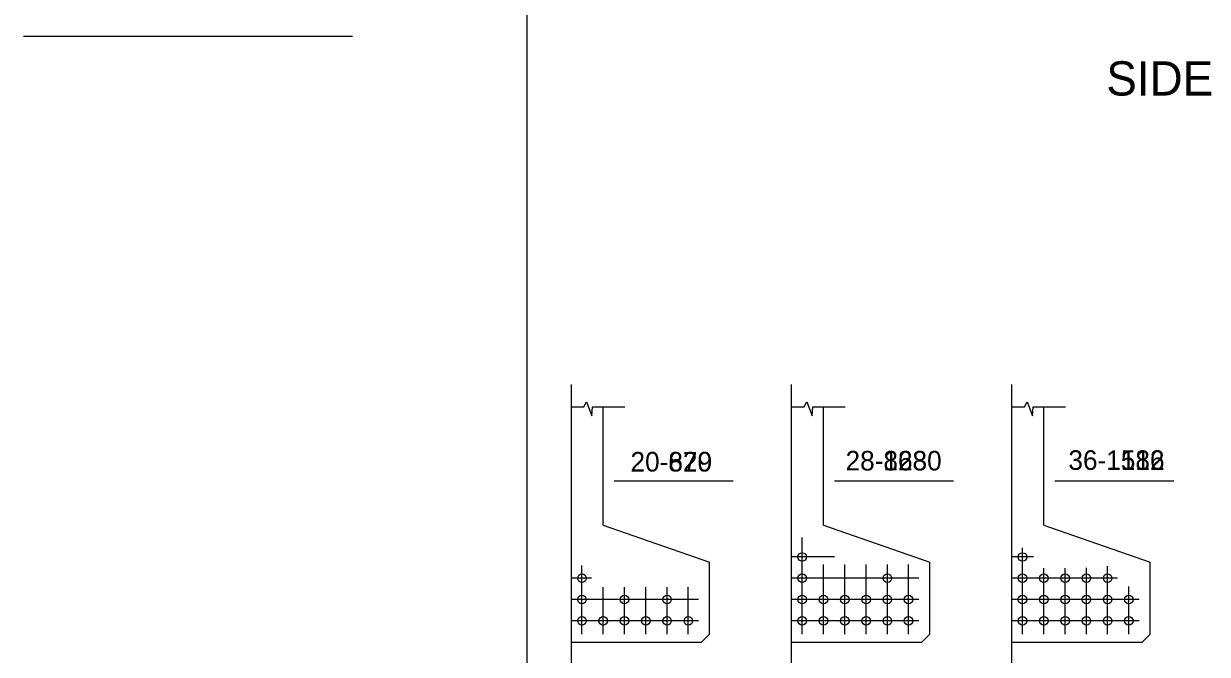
# Model space of a CAD drawing. Extents: x 1005.2 to 1101.8, y 1997.9 to 2073.7.
# Drawn here: x 1005.19 to 1025.34, y 2030.05 to 2040.78 of the extents above; entities that cross this region are included whole.
import ezdxf

# ---------------------------------------------------------------- set-up
doc = ezdxf.new("R2010")
doc.units = 0
for name, color, linetype in [('Level 1', 7, 'Continuous'), ('Level 2', 7, 'Continuous'), ('Level 37', 7, 'Continuous'), ('Level 8', 7, 'Continuous'), ('Level 9', 7, 'Continuous')]:
    doc.layers.add(name, color=color, linetype=linetype)

msp = doc.modelspace()

# ---------------------------------------------------------------- linework, layer by layer
at = {"layer": 'Level 1'}
msp.add_line((1013.763, 2012.562), (1013.763, 2068.561), dxfattribs=at)
at = {"layer": 'Level 37'}
msp.add_line((1010.791, 2040.561), (1005.193, 2040.561), dxfattribs=at)
at = {"layer": 'Level 8'}
for p, q in [((1014.516, 2014.747), (1014.516, 2034.639)), ((1018.266, 2014.747), (1018.266, 2034.639)), ((1022.016, 2014.747), (1022.016, 2034.639)), ((1014.516, 2034.258), (1014.729, 2034.258)), ((1014.729, 2034.258), (1014.776, 2034.347)), ((1014.776, 2034.347), (1014.865, 2034.104)), ((1014.865, 2034.104), (1014.878, 2034.258)), ((1014.878, 2034.258), (1015.427, 2034.258)), ((1015.06, 2032.248), (1015.06, 2034.258)), ((1018.266, 2034.258), (1018.479, 2034.258)), ((1018.479, 2034.258), (1018.526, 2034.347)), ((1018.526, 2034.347), (1018.615, 2034.104)), ((1018.615, 2034.104), (1018.628, 2034.258)), ((1018.628, 2034.258), (1019.177, 2034.258)), ((1018.81, 2032.248), (1018.81, 2034.258)), ((1022.016, 2034.258), (1022.229, 2034.258)), ((1022.229, 2034.258), (1022.276, 2034.347)), ((1022.276, 2034.347), (1022.365, 2034.104)), ((1022.365, 2034.104), (1022.378, 2034.258)), ((1022.378, 2034.258), (1022.927, 2034.258)), ((1022.56, 2032.248), (1022.56, 2034.258)), ((1015.244, 2032.998), (1017.269, 2032.998)), ((1018.994, 2032.998), (1021.019, 2032.998)), ((1022.744, 2032.998), (1024.769, 2032.998)), ((1015.06, 2032.248), (1016.869, 2031.614)), ((1018.81, 2032.248), (1020.619, 2031.614)), ((1022.56, 2032.248), (1024.369, 2031.614)), ((1018.447, 2030.392), (1018.447, 2032.035)), ((1022.197, 2030.392), (1022.197, 2031.859)), ((1016.869, 2030.392), (1016.869, 2031.614)), ((1018.994, 2031.704), (1018.266, 2031.704)), ((1018.809, 2030.392), (1018.809, 2031.576)), ((1019.171, 2030.392), (1019.171, 2031.576)), ((1019.533, 2030.392), (1019.533, 2031.576)), ((1019.895, 2030.392), (1019.895, 2031.576)), ((1020.257, 2030.392), (1020.257, 2031.576)), ((1020.619, 2030.392), (1020.619, 2031.614)), ((1022.383, 2031.704), (1022.016, 2031.704)), ((1024.369, 2030.392), (1024.369, 2031.614)), ((1014.697, 2030.392), (1014.697, 2031.558)), ((1022.559, 2030.392), (1022.559, 2031.512)), ((1022.921, 2030.392), (1022.921, 2031.516)), ((1023.283, 2030.392), (1023.283, 2031.52)), ((1023.645, 2030.392), (1023.645, 2031.55)), ((1014.858, 2031.342), (1014.516, 2031.342)), ((1015.059, 2030.392), (1015.059, 2031.188)), ((1015.421, 2030.392), (1015.421, 2031.188)), ((1015.783, 2030.392), (1015.783, 2031.188)), ((1016.145, 2030.392), (1016.145, 2031.188)), ((1016.507, 2030.392), (1016.507, 2031.188)), ((1020.431, 2031.342), (1018.266, 2031.342)), ((1023.811, 2031.342), (1022.016, 2031.342)), ((1024.007, 2030.392), (1024.007, 2031.201)), ((1016.681, 2030.98), (1014.516, 2030.98)), ((1020.431, 2030.98), (1018.266, 2030.98)), ((1024.181, 2030.98), (1022.016, 2030.98)), ((1016.681, 2030.618), (1014.516, 2030.618)), ((1020.431, 2030.618), (1018.266, 2030.618)), ((1024.181, 2030.618), (1022.016, 2030.618)), ((1016.733, 2030.256), (1016.869, 2030.392)), ((1020.483, 2030.256), (1020.619, 2030.392)), ((1024.233, 2030.256), (1024.369, 2030.392)), ((1014.516, 2030.256), (1016.733, 2030.256)), ((1018.266, 2030.256), (1020.483, 2030.256)), ((1022.016, 2030.256), (1024.233, 2030.256))]:
    msp.add_line(p, q, dxfattribs=at)
for centre in [(1018.447, 2031.704), (1022.197, 2031.704), (1014.697, 2031.342), (1018.447, 2031.342), (1022.197, 2031.342), (1022.559, 2031.342), (1022.921, 2031.342), (1023.283, 2031.342), (1023.645, 2031.342), (1014.697, 2030.98), (1015.421, 2030.98), (1016.145, 2030.98), (1018.447, 2030.98), (1018.809, 2030.98), (1019.171, 2030.98), (1019.533, 2030.98), (1019.895, 2030.98), (1020.257, 2030.98), (1022.197, 2030.98), (1022.559, 2030.98), (1022.921, 2030.98), (1023.283, 2030.98), (1023.645, 2030.98), (1024.007, 2030.98), (1014.697, 2030.618), (1015.059, 2030.618), (1015.421, 2030.618), (1015.783, 2030.618), (1016.145, 2030.618), (1016.507, 2030.618), (1018.447, 2030.618), (1018.809, 2030.618), (1019.171, 2030.618), (1019.533, 2030.618), (1019.895, 2030.618), (1020.257, 2030.618), (1022.197, 2030.618), (1022.559, 2030.618), (1022.921, 2030.618), (1023.283, 2030.618), (1023.645, 2030.618), (1024.007, 2030.618)]:
    msp.add_circle(centre, 0.073, dxfattribs=at)
at = {"layer": 'Level 9'}
for p, q in [((1014.516, 2014.747), (1014.516, 2034.639)), ((1018.266, 2014.747), (1018.266, 2034.639)), ((1022.016, 2014.747), (1022.016, 2034.639)), ((1014.516, 2034.258), (1014.729, 2034.258)), ((1014.729, 2034.258), (1014.776, 2034.347)), ((1014.776, 2034.347), (1014.865, 2034.104)), ((1014.865, 2034.104), (1014.878, 2034.258)), ((1014.878, 2034.258), (1015.427, 2034.258)), ((1015.06, 2032.248), (1015.06, 2034.258)), ((1018.266, 2034.258), (1018.479, 2034.258)), ((1018.479, 2034.258), (1018.526, 2034.347)), ((1018.526, 2034.347), (1018.615, 2034.104)), ((1018.615, 2034.104), (1018.628, 2034.258)), ((1018.628, 2034.258), (1019.177, 2034.258)), ((1018.81, 2032.248), (1018.81, 2034.258)), ((1022.016, 2034.258), (1022.229, 2034.258)), ((1022.229, 2034.258), (1022.276, 2034.347)), ((1022.276, 2034.347), (1022.365, 2034.104)), ((1022.365, 2034.104), (1022.378, 2034.258)), ((1022.378, 2034.258), (1022.927, 2034.258)), ((1022.56, 2032.248), (1022.56, 2034.258)), ((1015.244, 2032.998), (1017.269, 2032.998)), ((1018.994, 2032.998), (1021.019, 2032.998)), ((1022.744, 2032.998), (1024.769, 2032.998)), ((1015.06, 2032.248), (1016.869, 2031.614)), ((1018.81, 2032.248), (1020.619, 2031.614)), ((1022.56, 2032.248), (1024.369, 2031.614)), ((1022.197, 2030.392), (1022.197, 2031.859)), ((1016.869, 2030.392), (1016.869, 2031.614)), ((1018.447, 2030.392), (1018.447, 2031.576)), ((1018.809, 2030.392), (1018.809, 2031.576)), ((1019.171, 2030.392), (1019.171, 2031.576)), ((1019.533, 2030.392), (1019.533, 2031.576)), ((1019.895, 2030.392), (1019.895, 2031.576)), ((1020.257, 2030.392), (1020.257, 2031.576)), ((1020.619, 2030.392), (1020.619, 2031.614)), ((1022.383, 2031.704), (1022.016, 2031.704)), ((1024.369, 2030.392), (1024.369, 2031.614)), ((1014.697, 2030.392), (1014.697, 2031.558)), ((1022.559, 2030.392), (1022.559, 2031.512)), ((1022.921, 2030.392), (1022.921, 2031.516)), ((1023.283, 2030.392), (1023.283, 2031.52)), ((1023.645, 2030.392), (1023.645, 2031.55)), ((1014.858, 2031.342), (1014.516, 2031.342)), ((1015.059, 2030.392), (1015.059, 2031.188)), ((1015.421, 2030.392), (1015.421, 2031.188)), ((1015.783, 2030.392), (1015.783, 2031.188)), ((1016.145, 2030.392), (1016.145, 2031.188)), ((1016.507, 2030.392), (1016.507, 2031.188)), ((1020.431, 2031.342), (1018.266, 2031.342)), ((1023.811, 2031.342), (1022.016, 2031.342)), ((1024.007, 2030.392), (1024.007, 2031.201)), ((1016.681, 2030.98), (1014.516, 2030.98)), ((1020.431, 2030.98), (1018.266, 2030.98)), ((1024.181, 2030.98), (1022.016, 2030.98)), ((1016.681, 2030.618), (1014.516, 2030.618)), ((1020.431, 2030.618), (1018.266, 2030.618)), ((1024.181, 2030.618), (1022.016, 2030.618)), ((1016.733, 2030.256), (1016.869, 2030.392)), ((1020.483, 2030.256), (1020.619, 2030.392)), ((1024.233, 2030.256), (1024.369, 2030.392)), ((1014.516, 2030.256), (1016.733, 2030.256)), ((1018.266, 2030.256), (1020.483, 2030.256)), ((1022.016, 2030.256), (1024.233, 2030.256))]:
    msp.add_line(p, q, dxfattribs=at)
for centre in [(1022.197, 2031.704), (1014.697, 2031.342), (1018.447, 2031.342), (1019.895, 2031.342), (1022.197, 2031.342), (1022.559, 2031.342), (1022.921, 2031.342), (1023.283, 2031.342), (1023.645, 2031.342), (1014.697, 2030.98), (1015.421, 2030.98), (1016.145, 2030.98), (1018.447, 2030.98), (1018.809, 2030.98), (1019.171, 2030.98), (1019.533, 2030.98), (1019.895, 2030.98), (1020.257, 2030.98), (1022.197, 2030.98), (1022.559, 2030.98), (1022.921, 2030.98), (1023.283, 2030.98), (1023.645, 2030.98), (1024.007, 2030.98), (1014.697, 2030.618), (1015.059, 2030.618), (1015.421, 2030.618), (1015.783, 2030.618), (1016.145, 2030.618), (1016.507, 2030.618), (1018.447, 2030.618), (1018.809, 2030.618), (1019.171, 2030.618), (1019.533, 2030.618), (1019.895, 2030.618), (1020.257, 2030.618), (1022.197, 2030.618), (1022.559, 2030.618), (1022.921, 2030.618), (1023.283, 2030.618), (1023.645, 2030.618), (1024.007, 2030.618)]:
    msp.add_circle(centre, 0.073, dxfattribs=at)

# ---------------------------------------------------------------- texts
at = {"layer": 'Level 2'}
msp.add_text('             SIDE VIEW & TYPICAL SECTION IN SPAN', height=0.58333, dxfattribs=at).set_placement((1020.805, 2039.556))
at = {"layer": 'Level 8'}
for s, p in [('20-620', (1015.523, 2033.158)), ('28-868', (1019.184, 2033.176)), ('36-1116', (1022.977, 2033.186))]:
    msp.add_text(s, height=0.3333, dxfattribs=at).set_placement(p)
at = {"layer": 'Level 9'}
for s, p in [('20-879', (1015.523, 2033.158)), ('28-1230', (1019.184, 2033.176)), ('36-1582', (1022.977, 2033.186))]:
    msp.add_text(s, height=0.3333, dxfattribs=at).set_placement(p)

doc.saveas('drawing.dxf')
